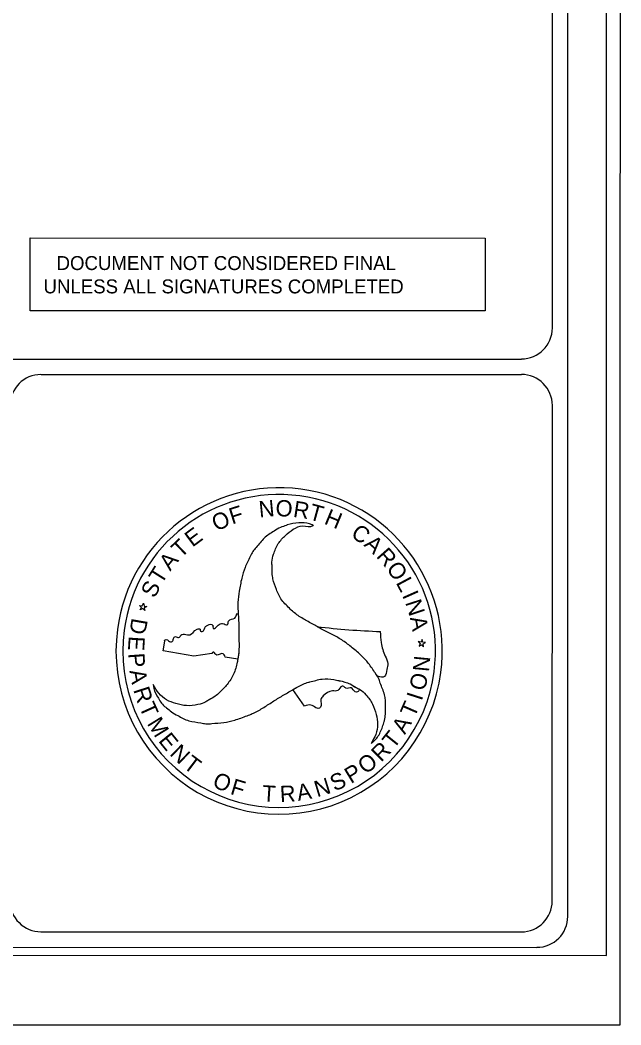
# Model space of a CAD drawing. Extents: x 2110629 to 2114002, y 669321 to 671542.
# Drawn here: x 2113194 to 2113528, y 669648 to 670207 of the extents above; entities that cross this region are included whole.
import ezdxf

# ---------------------------------------------------------------- set-up
doc = ezdxf.new("R2010")
doc.units = 0
for name, color, linetype in [('Exist Roads Curbs', 7, 'Continuous'), ('Exist Roads EOP Other Text', 7, 'Continuous'), ('Exist Structure Minor Catch Basin', 7, 'Continuous'), ('Exist Utilities Power Transformer Cogo Comment', 7, 'Continuous'), ('Exist Utilities Water Test Hole SUE LOS A Text', 7, 'Continuous')]:
    doc.layers.add(name, color=color, linetype=linetype)

msp = doc.modelspace()

# ---------------------------------------------------------------- linework, layer by layer
at = {"layer": 'Exist Roads Curbs'}
msp.add_line((2110628.92, 669648.68), (2113527.5, 669648.19), dxfattribs=at)
at = {"layer": 'Exist Roads EOP Other Text'}
msp.add_lwpolyline([(2110651.3, 669687.3), (2113519.77, 669686.81), (2113520.07, 671502.9), (2110651.61, 671503.39)], close=True, dxfattribs=at)
at = {"layer": 'Exist Structure Minor Catch Basin'}
for p, q in [((2111028.31, 670018.68), (2113472.49, 670018.27)), ((2113205.3, 670009.71), (2113472.49, 670009.66)), ((2113356.76, 669926.02), (2113356.58, 669925.85)), ((2113356.76, 669926.02), (2113356.58, 669925.85)), ((2113261.18, 669880.26), (2113260.06, 669881.36)), ((2113260.06, 669881.36), (2113261.63, 669881.15)), ((2113260.53, 669878.82), (2113261.18, 669880.26)), ((2113261.86, 669879.6), (2113260.53, 669878.82)), ((2113261.63, 669881.15), (2113262.25, 669882.53)), ((2113263.01, 669878.49), (2113261.86, 669879.6)), ((2113262.25, 669882.53), (2113262.59, 669881.02)), ((2113262.59, 669881.02), (2113264.13, 669880.81)), ((2113264.13, 669880.81), (2113262.73, 669880.05)), ((2113262.73, 669880.05), (2113263.01, 669878.49)), ((2113359.03, 669869.5), (2113359.03, 669869.5)), ((2113273.23, 669856.02), (2113274.14, 669861.41)), ((2113416.64, 669861.01), (2113415.09, 669861.22)), ((2113415.09, 669861.22), (2113416.25, 669860.14)), ((2113416.25, 669860.14), (2113415.6, 669858.71)), ((2113415.6, 669858.71), (2113416.92, 669859.45)), ((2113417.31, 669862.39), (2113416.64, 669861.01)), ((2113416.92, 669859.45), (2113418.05, 669858.38)), ((2113417.65, 669860.88), (2113417.31, 669862.39)), ((2113419.18, 669860.73), (2113417.65, 669860.88)), ((2113417.8, 669859.93), (2113419.18, 669860.73)), ((2113418.05, 669858.38), (2113417.8, 669859.93)), ((2113290.21, 669853.11), (2113273.23, 669856.02)), ((2113300.38, 669854.69), (2113290.21, 669853.11)), ((2113314.85, 669851.54), (2113307.74, 669852.56)), ((2113427.68, 669844.08), (2113427.68, 669844.08)), ((2113351.85, 669825.36), (2113345.39, 669834.55)), ((2113345.39, 669834.55), (2113345.39, 669834.55))]:
    msp.add_line(p, q, dxfattribs=at)
for points in [[(2113498.25, 669708.44), (2113498.55, 671481.3)], [(2113489.7, 670035.46), (2113489.95, 671472.72)], [(2113489.65, 669717.05), (2113489.7, 669992.45)], [(2113205.25, 669699.88), (2113472.43, 669699.84)], [(2110933.59, 669691.64), (2113481.04, 669691.21)]]:
    msp.add_lwpolyline(points, dxfattribs=at)
for centre, radius, start, end in [((2113472.5, 670035.56), 17.21, 269.9903, 359.9903), ((2113205.29, 669992.49), 17.21, 89.9903, 179.9903), ((2113472.49, 669992.53), 17.21, 359.9903, 89.9903), ((2113337.74, 669856.04), 90.74, 352.4114, 172.4114), ((2113337.74, 669856.04), 86.96, 352.4114, 172.4114), ((2113412.94, 670344.87), 478.41, 258.0899, 258.1895), ((2113412.94, 670344.87), 478.41, 263.529, 267.735), ((2113337.74, 669856.04), 90.74, 172.4114, 352.4114), ((2113337.74, 669856.04), 86.96, 172.4114, 352.4114), ((2113205.25, 669717.19), 17.21, 179.9903, 269.9903), ((2113472.44, 669717.13), 17.21, 269.9903, 359.9903), ((2113481.05, 669708.52), 17.21, 269.9903, 359.9903)]:
    msp.add_arc(centre, radius, start, end, dxfattribs=at)
for points in [[(2113356.58, 669925.85), (2113354.62, 669926.66), (2113348.62, 669927.21), (2113342.28, 669926.08), (2113341.71, 669925.85), (2113338.46, 669924.66), (2113334.91, 669922.69), (2113329.42, 669918.73), (2113324.93, 669913.55), (2113323.11, 669911.32), (2113321.62, 669908.48), (2113318.78, 669902.4), (2113316.92, 669896.41), (2113315.57, 669889.29), (2113314.84, 669882.98), (2113315.02, 669876.42), (2113315.28, 669869.79), (2113315.37, 669863.38), (2113315.39, 669856.78), (2113314.56, 669850.35), (2113314.46, 669849.8), (2113312.4, 669843.1), (2113308.83, 669837.47), (2113304.58, 669832.91), (2113302.17, 669830.87), (2113298.84, 669828.92), (2113296.96, 669827.79), (2113292.6, 669826.26), (2113286.25, 669825.64), (2113280.27, 669826.79), (2113275.12, 669828.86), (2113270.83, 669832.49), (2113267.7, 669837.31)], [(2113388.89, 669804.64), (2113390.47, 669805.89), (2113394, 669810.82), (2113396.19, 669816.88), (2113396.35, 669817.48), (2113396.86, 669820.91), (2113396.94, 669825), (2113396.32, 669831.73), (2113394.01, 669838.17), (2113393.04, 669840.88), (2113391.29, 669843.63), (2113387.46, 669849.11), (2113383.22, 669853.72), (2113377.71, 669858.41), (2113372.59, 669862.16), (2113366.81, 669865.37), (2113360.97, 669868.43), (2113355.42, 669871.53), (2113349.59, 669874.85), (2113344.5, 669878.76), (2113344.09, 669879.17), (2113339.24, 669884.32), (2113336.18, 669890.23), (2113334.31, 669896.15), (2113333.85, 669899.23), (2113333.82, 669903.11), (2113333.71, 669905.35), (2113334.64, 669909.84), (2113337.26, 669915.7), (2113341.21, 669920.25), (2113345.6, 669923.65), (2113350.92, 669925.55), (2113356.58, 669925.85), (2113356.76, 669926.02)], [(2113274.14, 669861.41), (2113274.02, 669861.94), (2113275, 669862.41), (2113277.4, 669861.03), (2113278.82, 669861.95), (2113278.92, 669863.05), (2113280.07, 669864.01), (2113281.76, 669863.43), (2113283.6, 669865.22), (2113285.09, 669865.38), (2113288.13, 669864.97), (2113292.21, 669868.12), (2113293.76, 669868.13), (2113294, 669867.12), (2113294.91, 669866.81), (2113296.85, 669869.59), (2113297.31, 669869.96), (2113300.28, 669870.71), (2113300.96, 669870.07), (2113301, 669868.71), (2113301.36, 669868.39), (2113302.38, 669868.93), (2113303.85, 669870.37), (2113306.33, 669871.26), (2113308.92, 669870.59), (2113309.66, 669872.68), (2113313.03, 669874.35), (2113313.84, 669875.52), (2113314.17, 669876.78)], [(2113315.01, 669876.58), (2113315.02, 669876.42), (2113315.28, 669869.79), (2113315.37, 669863.38), (2113315.39, 669856.78), (2113314.82, 669851.54)], [(2113392.5, 669841.92), (2113391.29, 669843.63), (2113387.46, 669849.11), (2113383.22, 669853.72), (2113377.71, 669858.41), (2113372.59, 669862.16), (2113366.81, 669865.37), (2113360.97, 669868.43), (2113359.03, 669869.5)], [(2113394.02, 669866.82), (2113394.5, 669860.65), (2113396.71, 669853.17), (2113398.22, 669849.03), (2113397.72, 669845.71), (2113396.42, 669841.84), (2113392.53, 669841.95)], [(2113307.74, 669852.56), (2113307.22, 669853.96), (2113305.89, 669854.55), (2113303.89, 669853.81), (2113302.49, 669854.08), (2113301.09, 669855.4), (2113300.38, 669854.69)], [(2113267.7, 669837.31), (2113268.07, 669835.2), (2113270.57, 669829.71), (2113274.68, 669824.76), (2113275.15, 669824.43), (2113277.86, 669822.14), (2113281.33, 669820.11), (2113287.52, 669817.27), (2113294.2, 669816.06), (2113297.03, 669815.55), (2113300.39, 669815.7), (2113306.93, 669816.29), (2113313.02, 669817.62), (2113319.91, 669820.04), (2113325.67, 669822.56), (2113331.34, 669826.01), (2113336.91, 669829.58), (2113342.45, 669832.83), (2113348.18, 669836.11), (2113354.13, 669838.65), (2113354.78, 669838.81), (2113361.61, 669840.4), (2113368.19, 669840.12), (2113374.2, 669838.77), (2113377.28, 669837.68), (2113380.52, 669835.71), (2113382.58, 669834.7), (2113386, 669831.67), (2113389.68, 669826.48), (2113391.69, 669820.79), (2113392.47, 669815.23), (2113391.46, 669809.69), (2113388.89, 669804.64)], [(2113345.39, 669834.55), (2113348.18, 669836.11), (2113354.13, 669838.65), (2113354.78, 669838.81), (2113361.61, 669840.4), (2113368.19, 669840.12), (2113374.2, 669838.77), (2113377.28, 669837.68), (2113380.52, 669835.71), (2113382.43, 669834.75)], [(2113382.4, 669834.72), (2113381.36, 669833.26), (2113379.99, 669833.34), (2113377.86, 669835.54), (2113374.88, 669835.34), (2113373.65, 669836.3), (2113372.77, 669836.44), (2113370.32, 669834.08), (2113367.35, 669833.82), (2113362.23, 669831.01), (2113361, 669829.14), (2113360.77, 669824.77), (2113359.51, 669824.07), (2113358.16, 669824.47), (2113355.43, 669825.97), (2113351.85, 669825.36)]]:
    msp.add_spline(points, degree=3, dxfattribs=at)
at = {"layer": 'Exist Utilities Power Transformer Cogo Comment'}
for p, q in [((2113199.24, 670045.14), (2113199.25, 670085.59)), ((2113199.25, 670085.59), (2113452.27, 670085.55)), ((2113452.27, 670085.53), (2113452.27, 670045.08)), ((2113452.27, 670045.1), (2113199.24, 670045.14))]:
    msp.add_line(p, q, dxfattribs=at)
at = {"layer": 'Exist Utilities Water Test Hole SUE LOS A Text'}
msp.add_lwpolyline([(2113527.82, 671541.54), (2110629.24, 671542.03), (2110628.92, 669648.68), (2113527.5, 669648.19)], close=True, dxfattribs=at)

# ---------------------------------------------------------------- texts
at = {"layer": 'Exist Structure Minor Catch Basin'}
for s, height, rotation, p in [('F', 9.07, 17.4822, (2113311.57, 669926.29)), ('N', 9.05, 5.3952, (2113326.82, 669930.2)), ('O', 9.07, 357.8971, (2113335.64, 669930.98)), ('R', 9.05, 351.2872, (2113345.19, 669930.63)), ('T', 9.07, 344.6375, (2113353.76, 669929.32)), ('O', 9.06, 24.629, (2113302.85, 669922.35)), ('H', 9.04, 337.5528, (2113362.28, 669926.91)), ('E', 9.02, 36.5684, (2113289.51, 669913.44)), ('C', 9.02, 325.2105, (2113377.08, 669919.89)), ('T', 9.03, 43.684, (2113283.08, 669907.35)), ('A', 9.04, 317.7134, (2113384.48, 669914.7)), ('R', 9.04, 311.3495, (2113391.35, 669908.47)), ('A', 9.08, 50.7392, (2113277.15, 669900.11)), ('T', 9.07, 57.7915, (2113272.34, 669892.69)), ('O', 9.06, 304.2299, (2113397.05, 669901.96)), ('L', 9.02, 297.9962, (2113402.47, 669893.99)), ('S', 9.04, 64.1677, (2113268.56, 669884.94)), ('I', 9.06, 294.0069, (2113405.99, 669887.01)), ('N', 9.04, 288.3068, (2113407.73, 669882.95)), ('A', 9.05, 280.8748, (2113410.46, 669874.5)), ('D', 9.05, 260.2644, (2113255.81, 669874.71)), ('E', 9.01, 266.5523, (2113254.14, 669864.45)), ('P', 9.05, 274.0847, (2113253.73, 669854.63)), ('N', 9.05, 84.6196, (2113421.05, 669844.2)), ('A', 9.03, 280.6773, (2113254.42, 669844.99)), ('O', 9.01, 77.3715, (2113418.75, 669833.52)), ('R', 9.05, 287.7459, (2113256.52, 669834.48)), ('I', 9.07, 72.2359, (2113417.04, 669827.97)), ('T', 9.04, 294.3965, (2113259.66, 669825)), ('T', 9.04, 66.586, (2113413.02, 669818.57)), ('M', 9.02, 301.6315, (2113264.03, 669815.71)), ('A', 9.07, 59.5016, (2113407.68, 669809.27)), ('E', 9.02, 309.0983, (2113270.23, 669806.01)), ('T', 9.02, 51.4145, (2113401.42, 669801.15)), ('N', 9.07, 316.0698, (2113276.48, 669798.5)), ('R', 9.06, 45.3148, (2113394.46, 669793.94)), ('T', 9.03, 322.9118, (2113283.9, 669791.49)), ('O', 9.07, 38.1257, (2113385.9, 669787.13)), ('P', 9.04, 31.4337, (2113377.68, 669782.01)), ('O', 9.04, 336.2155, (2113300.04, 669780.9)), ('F', 9.04, 343.3807, (2113310.11, 669776.63)), ('N', 9.02, 17.0313, (2113358.85, 669774.67)), ('S', 9.01, 24.2418, (2113368.58, 669777.85)), ('T', 9.02, 356.29, (2113328.14, 669772.49)), ('R', 9.05, 3.2466, (2113338.38, 669771.94)), ('A', 9.02, 9.9997, (2113348.35, 669772.65))]:
    msp.add_text(s, height=height, rotation=rotation, dxfattribs=at).set_placement(p)
at = {"layer": 'Exist Utilities Power Transformer Cogo Comment'}
for s, p in [('DOCUMENT NOT CONSIDERED FINAL', (2113213.95, 670067.78)), ('UNLESS ALL SIGNATURES COMPLETED', (2113206.7, 670054.8))]:
    msp.add_text(s, height=7.7456, rotation=359.9903, dxfattribs=at).set_placement(p)

doc.saveas('drawing.dxf')
